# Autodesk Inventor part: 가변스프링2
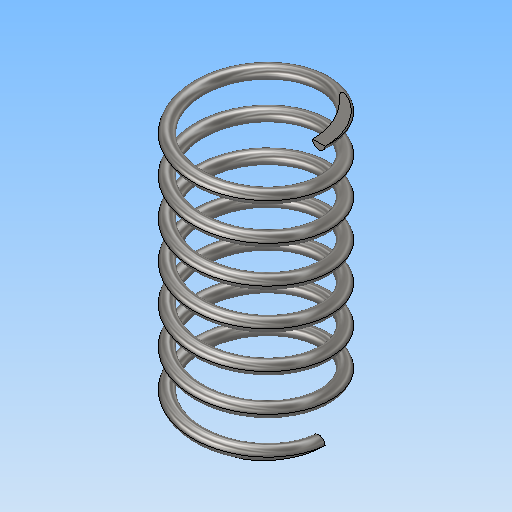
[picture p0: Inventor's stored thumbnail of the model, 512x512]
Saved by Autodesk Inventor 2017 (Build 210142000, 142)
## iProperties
Part Number: 가변스프링2
Material: 스테인레스 스틸
Document SubType Name: Modeling
Designer: MRC
Density: 8 g/cm^3
Appearance: 반연마
Mass: 10.94 g
Surface Area: 27.6363 cm^2
Volume: 1.36751 cm^3
Author: MRC
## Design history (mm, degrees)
sketch "스케치1"
  geometry: L1 (0, 0)-(10, 0); L2 (10, 0)-(10, 41.261); L3 (10, 41.261)-(0, 41.261); L4 (0, 41.261)-(0, 0); C1 r 1 at (10, 0)
  constraints: 8 end point, 2 parallel, 1 centre point, 1 coincident, 1 horizontal, 1 perpendicular
  dimensions: "d0" = 41.2612 distance between parallel lines of L1 L3 (derived); "d1" = 20 diameter of L2 L4; "d2" = 2 diameter of C1
feature "코일1" sketch "스케치1" pitch "d3" = 10; turns "d5" = 7; dims "d4" = 41.2612 (= d0), "d6" = 0, angle "d7" = 90 deg, angle "d8" = 90 deg, "d9" = 0, "d10" = 0
sketch "스케치2"
  geometry: L1 (0, -17.9)-(41.261, -17.9); L2 (41.261, -17.9)-(41.261, 17.9); L3 (41.261, 17.9)-(0, 17.9); L4 (0, 17.9)-(0, -17.9); 4 further points
  constraints: 8 end point, 2 coincident, 2 midpoint, 2 parallel, 1 horizontal, 1 perpendicular
  dimensions: "d11" = 35.80033 distance between parallel lines of L1 L3
extrude "돌출1" sketch "스케치2" stored distance "d12" = 50; taper "d13" = 0 deg
node "솔리드1"
